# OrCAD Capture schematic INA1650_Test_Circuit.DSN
size A; title: INA1650 SoundPlus™ High Common-Mode Rejection; rev: 1.4; note: Datasheet: SBOS818B    EVM: SBOU178
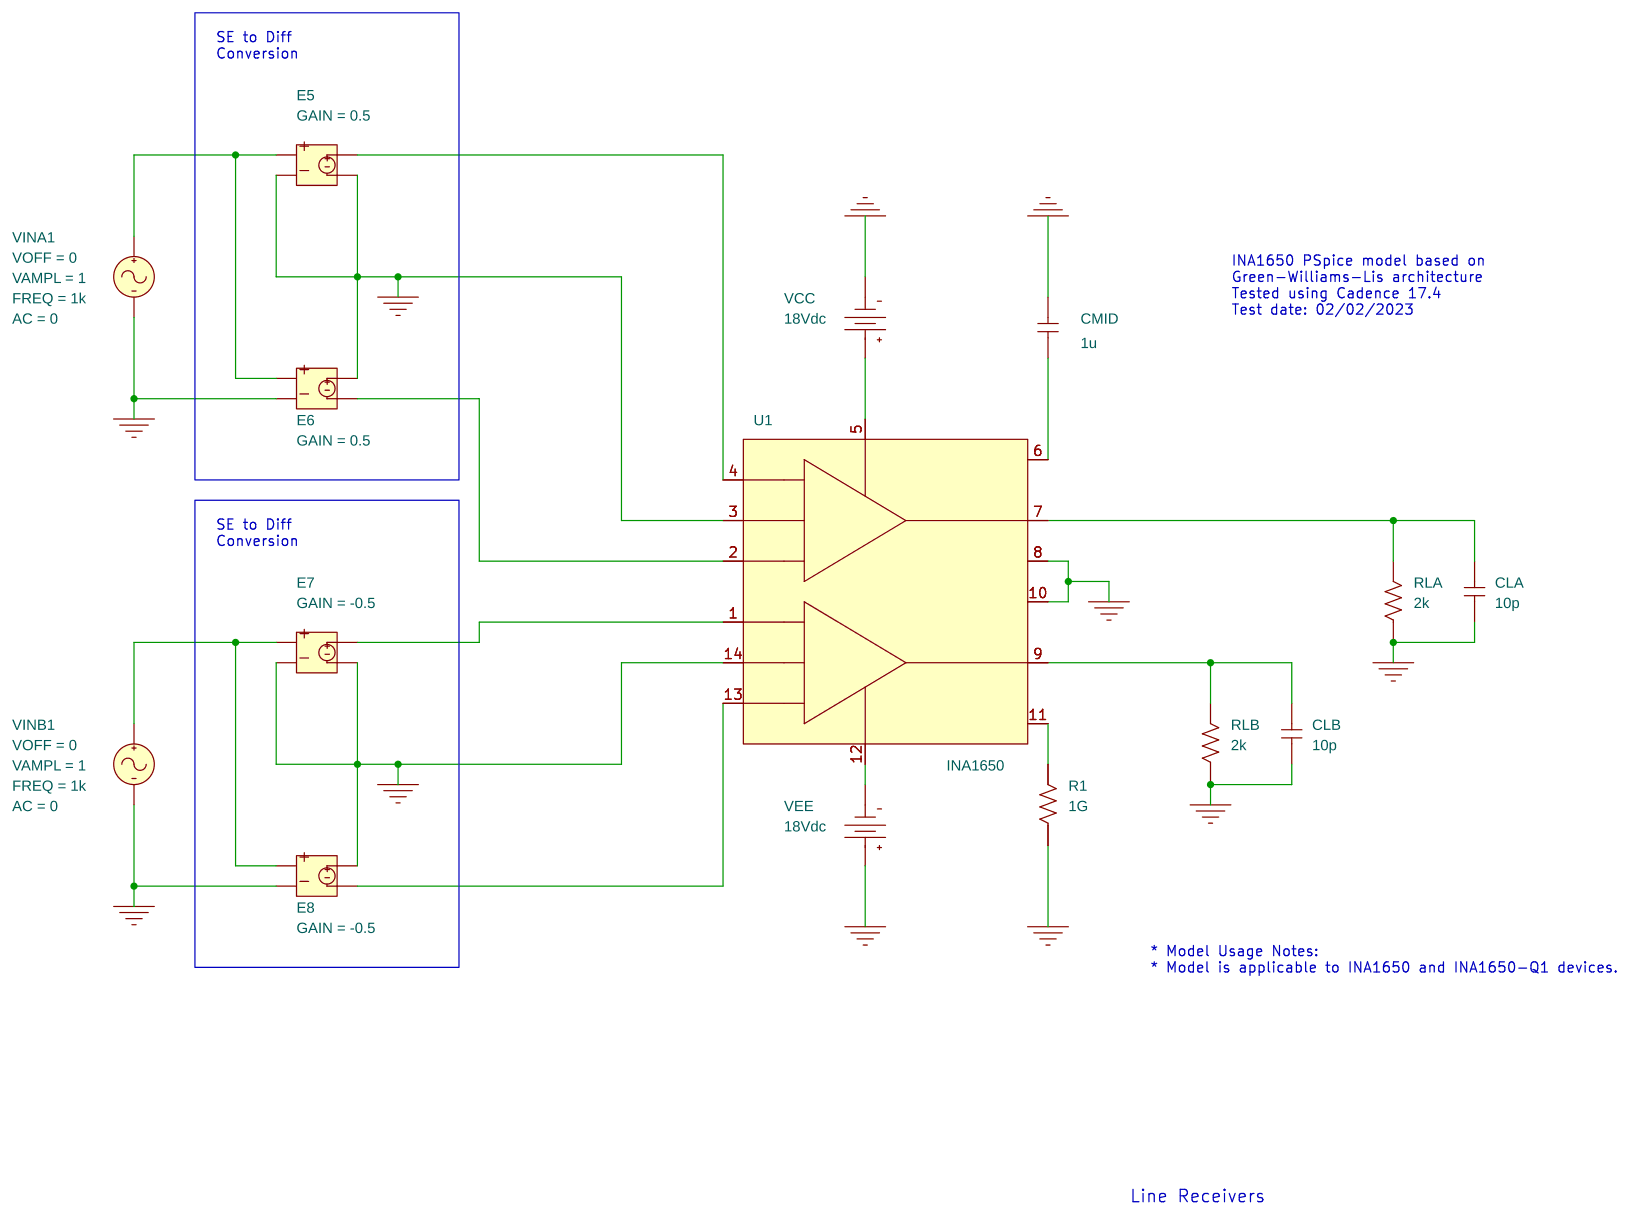
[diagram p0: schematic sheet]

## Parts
CLA  10p  [RAD/CK05]
CLB  10p  [RAD/CK05]
CMID  1u  [RAD/CK05]
E5  E
E6  E
E7  E
E8  E
R1  1G  [AX/RC05]
RLA  2k  [AX/RC05]
RLB  2k  [AX/RC05]
U1  INA1650
VCC  VDC
VEE  VDC
VINA1  VSIN
VINB1  VSIN

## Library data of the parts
CLA CLB CMID = C
E5 E6 = E: GAIN: 0.5
E7 E8 = E: GAIN: -0.5
R1 RLA RLB = R
U1 = INA1650
VCC VEE = VDC: DC: 18Vdc
VINA1 VINB1 = VSIN: AC: 0; FREQ: 1k; VAMPL: 1; VOFF: 0

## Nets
0: CLA.1 CLB.1 CMID.1 E5.2 E5.4 E6.2 E6.3 E7.2 E7.4 E8.2 E8.3 R1.1 RLA.1 RLB.1 U1.3(COMA) U1.8(REFA) U1.10(REFB) U1.14(COMB) VCC.1(-) VEE.0(+) VINA1.2(-) VINB1.2(-)
N16942: CLA.2 RLA.2 U1.7(OUTA)
N17185: CLB.2 RLB.2 U1.9(OUTB)
N36849: E5.1 E6.1 VINA1.1(+)
N36997: E6.4 U1.2(IN-A)
N37031: E7.3 U1.1(IN-B)
N37075: E8.4 U1.13(IN+B)
N37079: E7.1 E8.1 VINB1.1(+)
N38341: U1.5(V+) VCC.0(+)
N41268: CMID.2 U1.6(VMIDIN)
N41835: R1.2 U1.11(VMIDOUT)
N46860: U1.12(V-) VEE.1(-)
N46942: E5.3 U1.4(IN+A)

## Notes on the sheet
- SE to Diff
  Conversion
- INA1650 PSpice model based on
  Green-Williams-Lis architecture
  Tested using Cadence 17.4
  Test date: 02/02/2023
- SE to Diff
  Conversion
- * Model Usage Notes:
  * Model is applicable to INA1650 and INA1650-Q1 devices.
- Line Receivers
